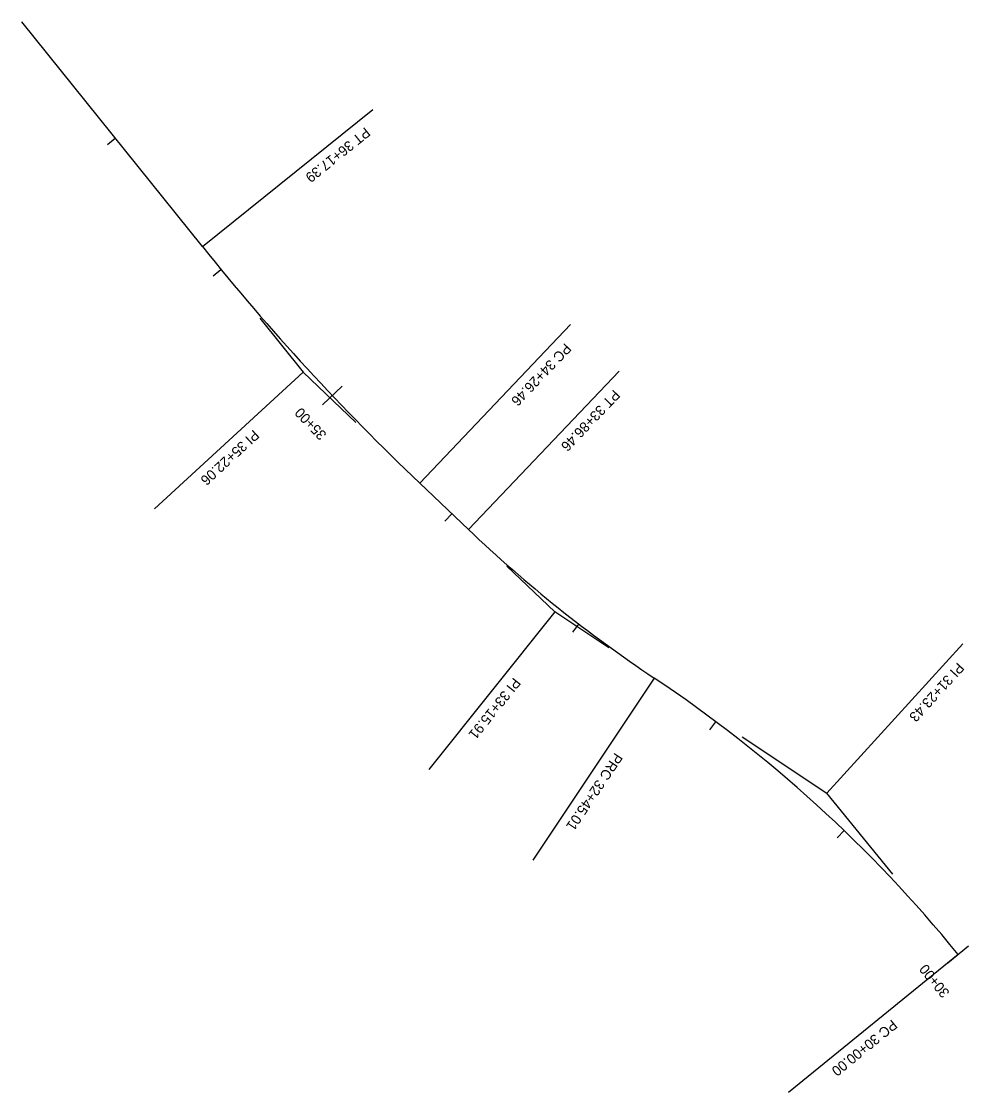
# Model space of a CAD drawing. Extents: x 955367 to 987800, y 1869413 to 1923417.
# Drawn here: x 955367 to 955930, y 1922780 to 1923417 of the extents above; entities that cross this region are included whole.
import ezdxf

# ---------------------------------------------------------------- set-up
doc = ezdxf.new("R2010")
doc.units = 0
doc.layers.add('R_Horz Alg', color=7, linetype='Continuous')
doc.layers.add('R_Horz Alg Annot', color=7, linetype='Continuous')

msp = doc.modelspace()

# ---------------------------------------------------------------- linework, layer by layer
at = {"layer": 'R_Horz Alg'}
for p, q in [((955474.39, 1923282.9), (955367.11, 1923416.43)), ((955632.49, 1923114.87), (955603.52, 1923142.44))]:
    msp.add_line(p, q, dxfattribs=at)
for centre, radius, start, end in [((956591.07, 1924179.99), 1432.39, 218.7769, 226.41419), ((956196.81, 1923707.75), 818.51, 226.41419, 236.31552), ((955288.89, 1922345.58), 818.51, 39.16489, 56.31552)]:
    msp.add_arc(centre, radius, start, end, dxfattribs=at)
at = {"layer": 'R_Horz Alg Annot'}
for p, q in [((955508.44, 1923240.51), (955534.27, 1923208.36)), ((955565.65, 1923178.49), (955534.27, 1923208.36)), ((955655.34, 1923093.12), (955683.85, 1923065.99)), ((955715.84, 1923044.67), (955683.85, 1923065.99)), ((955795.13, 1922991.82), (955845.55, 1922958.21)), ((955884.67, 1922910.18), (955845.55, 1922958.21))]:
    msp.add_line(p, q, dxfattribs=at)
for points in [[(955474.39, 1923282.9), (955575.74, 1923364.31)], [(955417.97, 1923343.54), (955422.65, 1923347.3)], [(955480.73, 1923265.59), (955485.36, 1923269.41)], [(955603.52, 1923142.44), (955693.15, 1923236.61)], [(955534.27, 1923208.36), (955445.93, 1923127.14)], [(955632.49, 1923114.87), (955722.12, 1923209.03)], [(955545.77, 1923188.99), (955557.38, 1923200)], [(955618.55, 1923119.86), (955622.68, 1923124.2)], [(955683.85, 1923065.99), (955608.93, 1922972.25)], [(955694.49, 1923053.92), (955698.15, 1923058.68)], [(955845.55, 1922958.21), (955926.25, 1923047.02)], [(955742.85, 1923026.66), (955670.75, 1922918.49)], [(955776, 1922995.88), (955779.59, 1923000.68)], [(955851.62, 1922931.67), (955855.77, 1922936)], [(955917.3, 1922857.46), (955929.71, 1922867.56)], [(955923.5, 1922862.51), (955822.71, 1922780.41)]]:
    msp.add_lwpolyline(points, dxfattribs=at)

# ---------------------------------------------------------------- texts
at = {"layer": 'R_Horz Alg'}
for rotation, p in [(128.7769, (955367.77, 1923416.41)), (128.7769, (955475.05, 1923282.87)), (136.41419, (955604.18, 1923142.51)), (136.41419, (955633.15, 1923114.93)), (146.31552, (955743.48, 1923026.84)), (129.16489, (955924.16, 1922862.49))]:
    msp.add_text('+', height=1, rotation=rotation, dxfattribs=at).set_placement(p)
at = {"layer": 'R_Horz Alg Annot'}
for s, rotation, p in [('PT 36+17.39', 218.7769, (955571.07, 1923354.15)), ('PC 34+26.46', 226.41419, (955689.88, 1923225.92)), ('PT 33+86.46', 226.41419, (955718.85, 1923198.34)), ('35+00', 133.47246, (955548.59, 1923171.48)), ('PI 35+22.06', 222.59555, (955504.8, 1923174.48)), ('PI 31+23.43', 227.74021, (955923.23, 1923036.26)), ('PI 33+15.91', 231.36486, (955659.35, 1923027.32)), ('PRC 32+45.01', 236.31552, (955719.55, 1922982.7)), ('30+00', 129.16489, (955918.8, 1922839.79)), ('PC 30+00.00', 219.16489, (955884.24, 1922824.08))]:
    msp.add_text(s, height=6, rotation=rotation, dxfattribs=at).set_placement(p)

doc.saveas('drawing.dxf')
